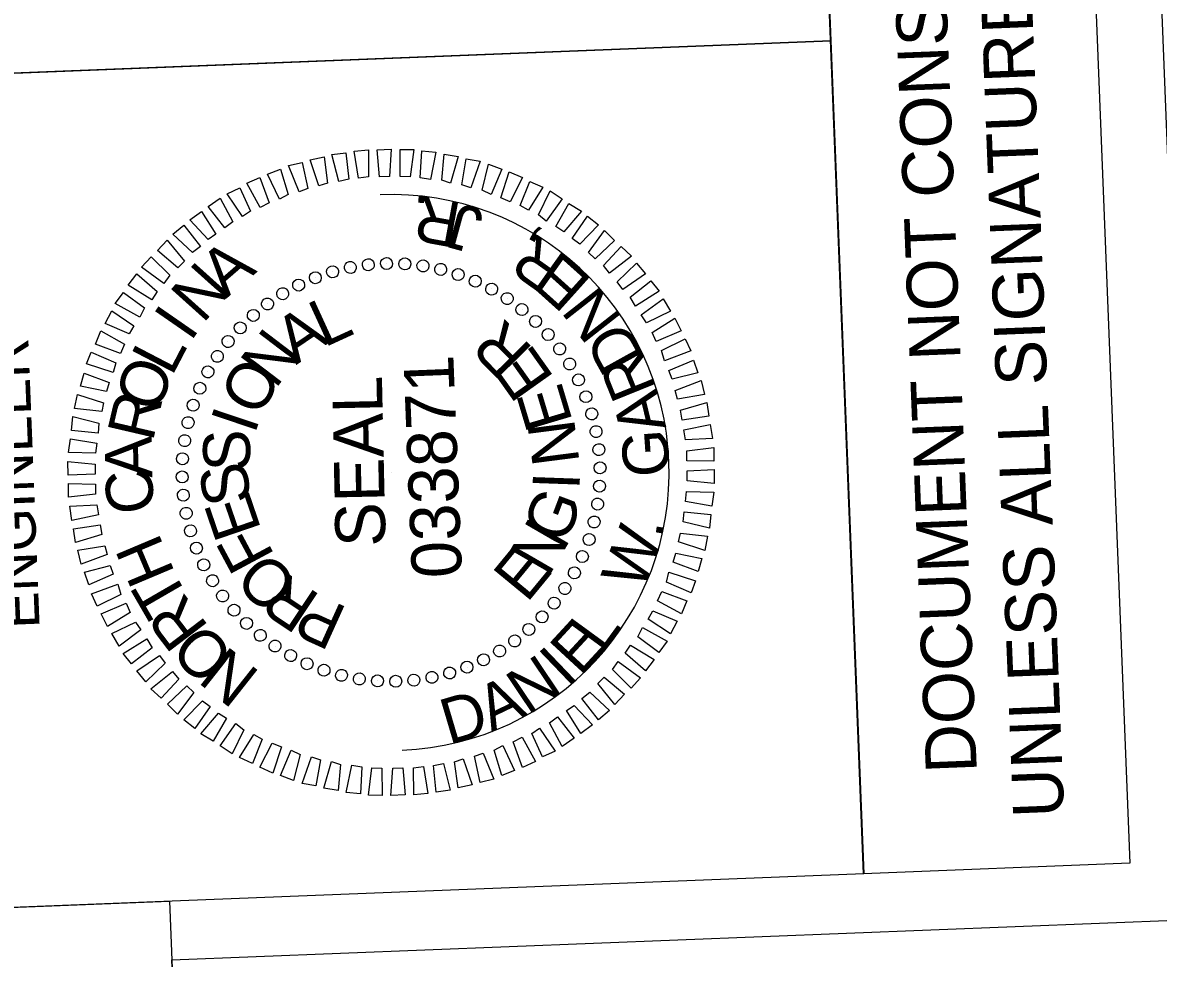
# Model space of a CAD drawing. Extents: x 1627905 to 1629071, y 761064 to 763101.
# Drawn here: x 1627988 to 1628124.3, y 762646.9 to 762759.2 of the extents above; entities that cross this region are included whole.
import ezdxf

# ---------------------------------------------------------------- set-up
doc = ezdxf.new("R2010")
doc.units = 0
for name, color, linetype in [('Old_Level_58', 7, 'Continuous'), ('Scratch_Level_0', 7, 'Continuous'), ('Sheet Clip Boundary CELL', 7, 'Continuous'), ('Sheet Plan And Profile CELL', 7, 'Continuous'), ('Sheet Professional Seal CELL', 7, 'Continuous'), ('Sheet Profile Grid Minor CELL', 7, 'Continuous'), ('Sheet Sticker Exception Certification CELL', 7, 'Continuous')]:
    doc.layers.add(name, color=color, linetype=linetype)

msp = doc.modelspace()

# ---------------------------------------------------------------- linework, layer by layer
at = {"layer": 'Old_Level_58'}
msp.add_lwpolyline([(1627946.91, 762451.28), (1627939.02, 762651.17), (1628005.66, 762653.8), (1628013.55, 762453.91)], close=True, dxfattribs=at)
at = {"layer": 'Scratch_Level_0'}
msp.add_arc((1628032.25, 762705.26), 33.36, 272.2582, 92.2582, dxfattribs=at)
at = {"layer": 'Sheet Clip Boundary CELL'}
msp.add_lwpolyline([(1628129.05, 762651.6), (1628122.74, 762811.67), (1628982.18, 762845.56), (1629039.43, 761393.61), (1627990.25, 761352.23), (1627946.91, 762451.28), (1628013.55, 762453.91), (1628005.94, 762646.74)], close=True, dxfattribs=at)
at = {"layer": 'Sheet Plan And Profile CELL'}
msp.add_line((1627972.6, 762752.63), (1628084.97, 762757.06), dxfattribs=at)
for points in [[(1627972.6, 762752.63), (1627968.66, 762852.55), (1628081.08, 762856.98), (1628085.02, 762757.06)], [(1627976.55, 762652.65), (1627972.6, 762752.63), (1628085.02, 762757.06), (1628088.96, 762657.09)]]:
    msp.add_lwpolyline(points, close=True, dxfattribs=at)
at = {"layer": 'Sheet Professional Seal CELL'}
for p, q in [((1628025.19, 762729.35), (1628025.19, 762729.35)), ((1628027.37, 762729.84), (1628027.37, 762729.84)), ((1628029.51, 762730.22), (1628029.51, 762730.22)), ((1628031.71, 762730.36), (1628031.71, 762730.36)), ((1628033.91, 762730.3), (1628033.91, 762730.3)), ((1628036.07, 762730.03), (1628036.07, 762730.03)), ((1628038.19, 762729.66), (1628038.19, 762729.66)), ((1628023.12, 762728.67), (1628023.12, 762728.67)), ((1628040.31, 762729.05), (1628040.31, 762729.05)), ((1628042.35, 762728.23), (1628042.35, 762728.23)), ((1628019.24, 762726.72), (1628019.24, 762726.72)), ((1628021.15, 762727.79), (1628021.15, 762727.79)), ((1628044.34, 762727.3), (1628044.34, 762727.3)), ((1628017.39, 762725.49), (1628017.39, 762725.49)), ((1628046.18, 762726.13), (1628046.18, 762726.13)), ((1628015.69, 762724.17), (1628015.69, 762724.17)), ((1628047.99, 762724.85), (1628047.99, 762724.85)), ((1628014.1, 762722.61), (1628014.1, 762722.61)), ((1628049.59, 762723.41), (1628049.59, 762723.41)), ((1628051.16, 762721.82), (1628051.16, 762721.82)), ((1628012.66, 762721), (1628012.66, 762721)), ((1628052.48, 762720.12), (1628052.48, 762720.12)), ((1628011.38, 762719.2), (1628011.38, 762719.2)), ((1628010.2, 762717.35), (1628010.2, 762717.35)), ((1628053.7, 762718.27), (1628053.7, 762718.27)), ((1628054.78, 762716.36), (1628054.78, 762716.36)), ((1628009.28, 762715.36), (1628009.28, 762715.36)), ((1628055.65, 762714.39), (1628055.65, 762714.39)), ((1628008.46, 762713.33), (1628008.46, 762713.33)), ((1628056.34, 762712.32), (1628056.34, 762712.32)), ((1628007.84, 762711.2), (1628007.84, 762711.2)), ((1628007.48, 762709.09), (1628007.48, 762709.09)), ((1628056.82, 762710.13), (1628056.82, 762710.13)), ((1628057.21, 762708), (1628057.21, 762708)), ((1628007.21, 762706.93), (1628007.21, 762706.93)), ((1628007.15, 762704.72), (1628007.15, 762704.72)), ((1628032.25, 762705.26), (1628032.25, 762705.26)), ((1628057.34, 762705.8), (1628057.34, 762705.8)), ((1628057.28, 762703.6), (1628057.28, 762703.6)), ((1628007.28, 762702.53), (1628007.28, 762702.53)), ((1628057.02, 762701.43), (1628057.02, 762701.43)), ((1628007.67, 762700.39), (1628007.67, 762700.39)), ((1628056.65, 762699.32), (1628056.65, 762699.32)), ((1628008.15, 762698.21), (1628008.15, 762698.21)), ((1628056.03, 762697.19), (1628056.03, 762697.19)), ((1628008.84, 762696.13), (1628008.84, 762696.13)), ((1628009.72, 762694.16), (1628009.72, 762694.16)), ((1628055.21, 762695.16), (1628055.21, 762695.16)), ((1628054.29, 762693.17), (1628054.29, 762693.17)), ((1628010.79, 762692.26), (1628010.79, 762692.26)), ((1628053.11, 762691.32), (1628053.11, 762691.32)), ((1628012.02, 762690.4), (1628012.02, 762690.4)), ((1628013.33, 762688.7), (1628013.33, 762688.7)), ((1628051.83, 762689.52), (1628051.83, 762689.52)), ((1628014.9, 762687.11), (1628014.9, 762687.11)), ((1628050.39, 762687.91), (1628050.39, 762687.91)), ((1628016.5, 762685.68), (1628016.5, 762685.68)), ((1628048.8, 762686.35), (1628048.8, 762686.35)), ((1628018.31, 762684.4), (1628018.31, 762684.4)), ((1628047.1, 762685.03), (1628047.1, 762685.03)), ((1628020.15, 762683.22), (1628020.15, 762683.22)), ((1628045.25, 762683.81), (1628045.25, 762683.81)), ((1628022.14, 762682.3), (1628022.14, 762682.3)), ((1628041.37, 762681.85), (1628041.37, 762681.85)), ((1628043.34, 762682.73), (1628043.34, 762682.73)), ((1628024.18, 762681.47), (1628024.18, 762681.47)), ((1628026.3, 762680.86), (1628026.3, 762680.86)), ((1628028.42, 762680.49), (1628028.42, 762680.49)), ((1628030.58, 762680.23), (1628030.58, 762680.23)), ((1628034.98, 762680.3), (1628034.98, 762680.3)), ((1628037.12, 762680.68), (1628037.12, 762680.68)), ((1628039.3, 762681.17), (1628039.3, 762681.17)), ((1628032.78, 762680.16), (1628032.78, 762680.16))]:
    msp.add_line(p, q, dxfattribs=at)
for points in [[(1628023.58, 762739.65), (1628022.51, 762742.76), (1628024.2, 762743.12), (1628024.62, 762739.99)], [(1628025.96, 762740.19), (1628025.14, 762743.41), (1628026.83, 762743.63), (1628027.16, 762740.44)], [(1628028.35, 762740.58), (1628027.82, 762743.82), (1628029.52, 762743.98), (1628029.55, 762740.73)], [(1628030.85, 762740.73), (1628030.57, 762743.97), (1628032.27, 762744.04), (1628032.05, 762740.78)], [(1628033.35, 762740.78), (1628033.32, 762744.03), (1628034.97, 762744), (1628034.55, 762740.73)], [(1628035.75, 762740.63), (1628035.93, 762743.84), (1628037.63, 762743.7), (1628036.96, 762740.42)], [(1628038.32, 762740.33), (1628038.6, 762743.44), (1628040.31, 762743.16), (1628039.38, 762739.97)], [(1628040.74, 762739.77), (1628041.27, 762742.9), (1628042.93, 762742.61), (1628041.81, 762739.41)], [(1628018.84, 762738.06), (1628017.42, 762741.05), (1628018.95, 762741.67), (1628019.87, 762738.6)], [(1628021.21, 762738.95), (1628019.93, 762742.1), (1628021.57, 762742.47), (1628022.24, 762739.34)], [(1628043.17, 762739.12), (1628043.95, 762742.25), (1628045.52, 762741.66), (1628044.24, 762738.61)], [(1628016.53, 762737.07), (1628014.91, 762739.96), (1628016.49, 762740.67), (1628017.61, 762737.61)], [(1628045.41, 762738.21), (1628046.43, 762741.35), (1628048.01, 762740.66), (1628046.53, 762737.75)], [(1628047.75, 762737.3), (1628048.88, 762740.19), (1628050.46, 762739.51), (1628048.72, 762736.73)], [(1628014.42, 762735.98), (1628012.56, 762738.71), (1628014.09, 762739.42), (1628015.35, 762736.62)], [(1628049.94, 762736.18), (1628051.33, 762739.04), (1628052.77, 762738.1), (1628050.87, 762735.42)], [(1628012.27, 762734.6), (1628010.27, 762737.17), (1628011.73, 762738.18), (1628013.25, 762735.34)], [(1628052, 762734.76), (1628053.59, 762737.53), (1628055.08, 762736.63), (1628052.97, 762734.15)], [(1628010.28, 762733.22), (1628008.08, 762735.58), (1628009.49, 762736.59), (1628011.2, 762733.85)], [(1628008.39, 762731.64), (1628006.05, 762733.85), (1628007.36, 762734.95), (1628009.36, 762732.38)], [(1628053.96, 762733.34), (1628055.8, 762736.01), (1628057.14, 762734.97), (1628054.88, 762732.67)], [(1628055.92, 762731.66), (1628057.87, 762734.29), (1628059.07, 762733.09), (1628056.75, 762730.9)], [(1628006.66, 762729.82), (1628004.22, 762731.88), (1628005.38, 762733.12), (1628007.43, 762730.6)], [(1628057.74, 762730.08), (1628059.85, 762732.37), (1628061.09, 762731.22), (1628058.47, 762729.16)], [(1628004.98, 762727.95), (1628002.3, 762729.9), (1628003.45, 762731.15), (1628005.69, 762728.93)], [(1628059.36, 762728.15), (1628061.68, 762730.39), (1628062.78, 762729.08), (1628060.05, 762727.22)], [(1628003.51, 762725.99), (1628000.69, 762727.73), (1628001.73, 762729.08), (1628004.17, 762726.97)], [(1628060.94, 762726.31), (1628063.41, 762728.26), (1628064.41, 762727), (1628061.58, 762725.23)], [(1628002.09, 762723.89), (1627999.12, 762725.52), (1628000.12, 762726.86), (1628002.64, 762725.01)], [(1628062.27, 762724.16), (1628064.9, 762726.11), (1628065.76, 762724.6), (1628062.91, 762723.23)], [(1628000.82, 762721.89), (1627997.91, 762723.12), (1627998.71, 762724.65), (1628001.38, 762722.86)], [(1628063.56, 762722.06), (1628066.29, 762723.77), (1628067.05, 762722.25), (1628064.05, 762720.98)], [(1627999.76, 762719.54), (1627996.76, 762720.67), (1627997.4, 762722.25), (1628000.26, 762720.66)], [(1628064.69, 762719.9), (1628067.54, 762721.31), (1628068.2, 762719.84), (1628065.04, 762718.66)], [(1627998.9, 762717.26), (1627995.7, 762718.28), (1627996.25, 762719.7), (1627999.2, 762718.42)], [(1628065.59, 762717.48), (1628068.54, 762718.75), (1628069.05, 762717.22), (1628065.98, 762716.45)], [(1627998.09, 762714.97), (1627994.96, 762715.6), (1627995.4, 762717.17), (1627998.39, 762716.04)], [(1628066.33, 762715.11), (1628069.44, 762716.29), (1628069.86, 762714.6), (1628066.62, 762714.07)], [(1627997.53, 762712.55), (1627994.26, 762712.92), (1627994.6, 762714.63), (1627997.74, 762713.61)], [(1628066.98, 762712.74), (1628070.14, 762713.66), (1628070.36, 762712.02), (1628067.17, 762711.54)], [(1627997.08, 762709.98), (1627993.87, 762710.3), (1627994.05, 762711.96), (1627997.18, 762711.18)], [(1628067.37, 762710.35), (1628070.55, 762711.02), (1628070.81, 762709.33), (1628067.57, 762709.16)], [(1627996.78, 762707.57), (1627993.52, 762707.64), (1627993.76, 762709.3), (1627996.93, 762708.77)], [(1628067.72, 762707.86), (1628070.96, 762708.24), (1628070.97, 762706.59), (1628067.72, 762706.66)], [(1627996.73, 762705.06), (1627993.48, 762704.93), (1627993.46, 762706.58), (1627996.73, 762706.26)], [(1628067.77, 762705.46), (1628071.01, 762705.59), (1628071.03, 762703.94), (1628067.76, 762704.26)], [(1627996.77, 762702.66), (1627993.53, 762702.28), (1627993.52, 762703.93), (1627996.77, 762703.86)], [(1628067.71, 762702.96), (1628070.97, 762702.88), (1628070.73, 762701.22), (1628067.56, 762701.75)], [(1627997.12, 762700.17), (1627993.94, 762699.5), (1627993.68, 762701.19), (1627996.92, 762701.37)], [(1628067.41, 762700.54), (1628070.62, 762700.22), (1628070.44, 762698.56), (1628067.31, 762699.34)], [(1627997.51, 762697.79), (1627994.35, 762696.86), (1627994.13, 762698.5), (1627997.32, 762698.98)], [(1628066.96, 762697.97), (1628070.23, 762697.6), (1628069.89, 762695.89), (1628066.75, 762696.91)], [(1627998.16, 762695.41), (1627995.05, 762694.24), (1627994.63, 762695.92), (1627997.87, 762696.45)], [(1628066.4, 762695.55), (1628069.53, 762694.92), (1628069.09, 762693.35), (1628066.1, 762694.49)], [(1627998.9, 762693.04), (1627995.95, 762691.77), (1627995.44, 762693.3), (1627998.51, 762694.07)], [(1628065.59, 762693.27), (1628068.79, 762692.24), (1628068.24, 762690.82), (1628065.29, 762692.1)], [(1627999.8, 762690.62), (1627996.95, 762689.21), (1627996.29, 762690.68), (1627999.45, 762691.86)], [(1628064.73, 762690.98), (1628067.73, 762689.85), (1628067.09, 762688.27), (1628064.23, 762689.86)], [(1628000.93, 762688.46), (1627998.2, 762686.76), (1627997.44, 762688.28), (1628000.44, 762689.55)], [(1628063.67, 762688.64), (1628066.58, 762687.4), (1628065.79, 762685.87), (1628063.11, 762687.66)], [(1628002.22, 762686.36), (1627999.59, 762684.41), (1627998.73, 762685.93), (1628001.58, 762687.29)], [(1628062.4, 762686.63), (1628065.37, 762685), (1628064.37, 762683.66), (1628061.85, 762685.51)], [(1628003.55, 762684.21), (1628001.08, 762682.27), (1628000.08, 762683.53), (1628002.91, 762685.29)], [(1628060.98, 762684.53), (1628063.81, 762682.79), (1628062.76, 762681.44), (1628060.32, 762683.55)], [(1628005.13, 762682.37), (1628002.81, 762680.13), (1628001.71, 762681.44), (1628004.44, 762683.3)], [(1628059.51, 762682.57), (1628062.19, 762680.62), (1628061.04, 762679.38), (1628058.8, 762681.59)], [(1628006.75, 762680.44), (1628004.64, 762678.15), (1628003.4, 762679.3), (1628006.02, 762681.36)], [(1628057.83, 762680.7), (1628060.27, 762678.64), (1628059.11, 762677.4), (1628057.06, 762679.92)], [(1628008.57, 762678.86), (1628006.62, 762676.23), (1628005.42, 762677.43), (1628007.74, 762679.63)], [(1628056.1, 762678.88), (1628058.44, 762676.67), (1628057.13, 762675.57), (1628055.13, 762678.14)], [(1628010.53, 762677.18), (1628008.69, 762674.51), (1628007.35, 762675.56), (1628009.61, 762677.85)], [(1628012.49, 762675.76), (1628010.9, 762672.99), (1628009.41, 762673.89), (1628011.52, 762676.37)], [(1628054.21, 762677.3), (1628056.41, 762674.94), (1628055, 762673.93), (1628053.29, 762676.67)], [(1628014.55, 762674.34), (1628013.16, 762671.48), (1628011.72, 762672.43), (1628013.62, 762675.1)], [(1628052.22, 762675.93), (1628054.22, 762673.35), (1628052.76, 762672.34), (1628051.25, 762675.19)], [(1628016.75, 762673.23), (1628015.61, 762670.33), (1628014.03, 762671.02), (1628015.77, 762673.79)], [(1628047.96, 762673.46), (1628049.58, 762670.57), (1628048, 762669.85), (1628046.88, 762672.91)], [(1628050.07, 762674.54), (1628051.93, 762671.81), (1628050.41, 762671.1), (1628049.14, 762673.9)], [(1628019.08, 762672.32), (1628018.06, 762669.17), (1628016.48, 762669.86), (1628017.96, 762672.77)], [(1628045.65, 762672.46), (1628047.07, 762669.47), (1628045.54, 762668.86), (1628044.62, 762671.92)], [(1628021.32, 762671.4), (1628020.54, 762668.27), (1628018.97, 762668.86), (1628020.25, 762671.91)], [(1628023.75, 762670.75), (1628023.22, 762667.63), (1628021.56, 762667.91), (1628022.68, 762671.11)], [(1628040.91, 762670.88), (1628041.98, 762667.77), (1628040.29, 762667.4), (1628039.87, 762670.53)], [(1628043.28, 762671.57), (1628044.56, 762668.42), (1628042.92, 762668.05), (1628042.25, 762671.18)], [(1628026.17, 762670.19), (1628025.89, 762667.08), (1628024.18, 762667.36), (1628025.11, 762670.55)], [(1628028.74, 762669.9), (1628028.56, 762666.69), (1628026.86, 762666.82), (1628027.53, 762670.1)], [(1628031.14, 762669.74), (1628031.17, 762666.49), (1628029.52, 762666.52), (1628029.94, 762669.79)], [(1628033.64, 762669.79), (1628033.92, 762666.55), (1628032.22, 762666.48), (1628032.45, 762669.74)], [(1628036.14, 762669.94), (1628036.67, 762666.71), (1628034.97, 762666.54), (1628034.95, 762669.79)], [(1628038.53, 762670.33), (1628039.35, 762667.11), (1628037.66, 762666.89), (1628037.34, 762670.08)]]:
    msp.add_lwpolyline(points, close=True, dxfattribs=at)
for centre, major_axis in [((1628027.35, 762729.86), (-0.141, 0.706)), ((1628029.51, 762730.19), (-0.078, 0.716)), ((1628031.69, 762730.33), (-0.016, 0.72)), ((1628033.88, 762730.29), (0.047, 0.718)), ((1628036.06, 762730.05), (0.109, 0.712)), ((1628023.15, 762728.63), (-0.261, 0.671)), ((1628025.22, 762729.34), (-0.202, 0.691)), ((1628038.2, 762729.62), (0.171, 0.699)), ((1628040.3, 762729.01), (0.231, 0.682)), ((1628021.15, 762727.75), (-0.319, 0.646)), ((1628042.34, 762728.22), (0.29, 0.659)), ((1628044.31, 762727.25), (0.346, 0.631)), ((1628019.23, 762726.7), (-0.374, 0.615)), ((1628046.18, 762726.12), (0.4, 0.599)), ((1628017.41, 762725.48), (-0.426, 0.581)), ((1628047.94, 762724.82), (0.451, 0.562)), ((1628015.71, 762724.11), (-0.475, 0.541)), ((1628049.59, 762723.38), (0.498, 0.52)), ((1628014.13, 762722.6), (-0.52, 0.498)), ((1628051.1, 762721.8), (0.541, 0.475)), ((1628012.68, 762720.96), (-0.562, 0.451)), ((1628011.39, 762719.19), (-0.599, 0.4)), ((1628052.47, 762720.09), (0.581, 0.426)), ((1628053.68, 762718.27), (0.615, 0.374)), ((1628010.26, 762717.32), (-0.631, 0.346)), ((1628054.74, 762716.36), (0.646, 0.319)), ((1628009.29, 762715.36), (-0.659, 0.29)), ((1628055.62, 762714.35), (0.671, 0.261)), ((1628008.5, 762713.32), (-0.682, 0.231)), ((1628056.32, 762712.28), (0.691, 0.202)), ((1628007.88, 762711.22), (-0.699, 0.171)), ((1628056.84, 762710.16), (0.706, 0.141)), ((1628007.46, 762709.07), (-0.712, 0.109)), ((1628007.22, 762706.9), (-0.718, 0.047)), ((1628057.18, 762707.99), (0.716, 0.078)), ((1628057.32, 762705.81), (0.72, 0.016)), ((1628007.17, 762704.71), (-0.72, -0.016)), ((1628057.27, 762703.62), (0.718, -0.047)), ((1628007.31, 762702.53), (-0.716, -0.078)), ((1628057.03, 762701.45), (0.712, -0.109)), ((1628007.65, 762700.36), (-0.706, -0.141)), ((1628056.61, 762699.3), (0.699, -0.171)), ((1628008.17, 762698.24), (-0.691, -0.202)), ((1628056, 762697.2), (0.682, -0.231)), ((1628008.87, 762696.17), (-0.671, -0.261)), ((1628055.2, 762695.16), (0.659, -0.29)), ((1628009.75, 762694.17), (-0.646, -0.319)), ((1628054.24, 762693.2), (0.631, -0.346)), ((1628010.81, 762692.25), (-0.615, -0.374)), ((1628012.02, 762690.43), (-0.581, -0.426)), ((1628053.1, 762691.33), (0.599, -0.4)), ((1628051.81, 762689.57), (0.562, -0.451)), ((1628013.39, 762688.72), (-0.541, -0.475)), ((1628050.36, 762687.92), (0.52, -0.498)), ((1628014.9, 762687.14), (-0.498, -0.52)), ((1628048.78, 762686.41), (0.475, -0.541)), ((1628016.55, 762685.7), (-0.451, -0.562)), ((1628047.08, 762685.04), (0.426, -0.581)), ((1628018.31, 762684.41), (-0.4, -0.599)), ((1628045.26, 762683.82), (0.374, -0.615)), ((1628020.19, 762683.27), (-0.346, -0.631)), ((1628022.15, 762682.3), (-0.29, -0.659)), ((1628043.34, 762682.77), (0.319, -0.646)), ((1628024.19, 762681.51), (-0.231, -0.682)), ((1628026.29, 762680.9), (-0.171, -0.699)), ((1628039.27, 762681.18), (0.202, -0.691)), ((1628041.34, 762681.89), (0.261, -0.671)), ((1628028.43, 762680.47), (-0.109, -0.712)), ((1628030.61, 762680.23), (-0.047, -0.718)), ((1628032.8, 762680.19), (0.016, -0.72)), ((1628034.98, 762680.33), (0.078, -0.716)), ((1628037.14, 762680.66), (0.141, -0.706))]:
    msp.add_ellipse(centre, major_axis=major_axis, ratio=0.999708, dxfattribs=at)
at = {"layer": 'Sheet Sticker Exception Certification CELL'}
for p, q in [((1628113.01, 762858.24), (1628120.9, 762658.35)), ((1628088.94, 762657.09), (1628081.06, 762856.98)), ((1628120.9, 762658.35), (1628088.94, 762657.09))]:
    msp.add_line(p, q, dxfattribs=at)

# ---------------------------------------------------------------- texts
at = {"layer": 'Sheet Plan And Profile CELL'}
msp.add_text('ENGINEER', height=5, rotation=92.2582, dxfattribs=at).set_placement((1627990.07, 762686.56))
at = {"layer": 'Sheet Professional Seal CELL'}
for s, height, rotation, p in [('A', 5.64, 40.8753, (1628012.46, 762726.1)), ('N', 5.64, 48.0771, (1628009.63, 762723.03)), ('I', 5.64, 55.2783, (1628008.16, 762720.82)), ('L', 5.64, 24.659, (1628024.2, 762720.21)), ('A', 5.64, 34.0185, (1628020.83, 762718.12)), ('R', 5.64, 134.7396, (1628049.43, 762720.05)), ('N', 5.64, 52.7348, (1628018.34, 762715.17)), ('L', 5.64, 62.4791, (1628005.92, 762716.68)), ('E', 5.64, 125.3823, (1628051.91, 762716.59)), ('O', 5.64, 69.6794, (1628004.25, 762712.21)), ('O', 5.64, 62.0917, (1628016.48, 762711.74)), ('SEAL', 5.998, 91.2582, (1628031.59, 762696.38)), ('E', 5.64, 106.67, (1628054.07, 762711.38)), ('R', 5.64, 76.8793, (1628003.63, 762708.84)), ('I', 5.64, 71.4478, (1628015.86, 762709.72)), ('N', 5.64, 97.3146, (1628054.87, 762706.45)), ('A', 5.64, 91.2785, (1628003.6, 762704.63)), ('S', 5.64, 90.1586, (1628015.33, 762705.39)), ('S', 5.64, 99.5138, (1628015.52, 762701.8)), ('C', 5.64, 98.4781, (1628004.05, 762700.7)), ('I', 5.64, 87.9594, (1628054.85, 762703.1)), ('E', 5.64, 108.8693, (1628016.7, 762698.39)), ('G', 5.64, 69.2484, (1628053.21, 762696.48)), ('N', 5.64, 59.8921, (1628051.11, 762692.59)), ('H', 5.64, 112.8777, (1628006.35, 762693.18)), ('F', 5.64, 118.2252, (1628018.33, 762695.25)), ('E', 5.64, 50.5351, (1628048.53, 762689.49)), ('O', 5.64, 136.9394, (1628021.41, 762692.07)), ('R', 5.64, 146.2978, (1628023.92, 762690.42)), ('T', 5.64, 120.078, (1628008.13, 762690)), ('R', 5.64, 127.2787, (1628010.46, 762686.69)), ('P', 5.64, 155.6571, (1628027.18, 762688.95)), ('O', 5.64, 134.4799, (1628013.69, 762683.36)), ('N', 5.64, 141.6817, (1628016.68, 762681.18))]:
    msp.add_text(s, height=height, rotation=rotation, dxfattribs=at).set_placement(p)
at = {"layer": 'Sheet Profile Grid Minor CELL'}
for s, height, rotation, p in [('R', 5.5, 169.6122, (1628040.88, 762737.6)), ('.', 5.5, 176.5387, (1628036.92, 762738.4)), ('J', 5.5, 164.7437, (1628043.59, 762736.75)), (',', 5.5, 151.5634, (1628050.47, 762733.33)), ('R', 5.5, 144.637, (1628053.73, 762730.93)), ('E', 5.5, 138.054, (1628056.53, 762728.3)), ('N', 5.5, 128.1223, (1628060.14, 762723.76)), ('D', 5.5, 118.9777, (1628062.72, 762719.1)), ('R', 5.5, 112.0512, (1628064.17, 762715.32)), ('033871', 5.998, 92.2582, (1628040.76, 762692.69)), ('A', 5.5, 103.8654, (1628065.28, 762710.67)), ('G', 5.5, 93.9337, (1628065.71, 762704.89)), ('W', 5.5, 69.1473, (1628062.48, 762690.9)), ('.', 5.5, 80.7534, (1628064.75, 762697.27)), ('E', 5.5, 47.309, (1628054.96, 762680.68)), ('L', 5.5, 53.892, (1628057.63, 762683.45)), ('N', 5.5, 33.8568, (1628048.62, 762676.07)), ('I', 5.5, 43.7885, (1628053.41, 762679.33)), ('A', 5.5, 25.671, (1628044.3, 762674.04)), ('D', 5.5, 16.5264, (1628039.18, 762672.52))]:
    msp.add_text(s, height=height, rotation=rotation, dxfattribs=at).set_placement(p)
at = {"layer": 'Sheet Sticker Exception Certification CELL'}
for s, p in [('UNLESS ALL SIGNATURES COMPLETED', (1628113.03, 762663.93)), ('DOCUMENT NOT CONSIDERED FINAL', (1628102.55, 762669.26))]:
    msp.add_text(s, height=6.124, rotation=92.2582, dxfattribs=at).set_placement(p)

doc.saveas('drawing.dxf')
